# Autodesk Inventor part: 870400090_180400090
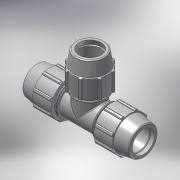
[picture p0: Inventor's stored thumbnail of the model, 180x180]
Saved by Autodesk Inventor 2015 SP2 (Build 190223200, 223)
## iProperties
Created: 2017-02
Part Number: 870400090_180400090
Material: PVC-Piping
Description: PLASSON TEE 90-90-90
Document SubType Name: Modeling
Designer: KIM
Mass: 92.6774 g
Surface Area: 199.44 cm^2
Volume: 66.1981 cm^3
Density: 1.4 g/cm^3
Appearance: Smooth - White
Author: KIM
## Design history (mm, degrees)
derived "87040.ipt"
feature "Solid1::87040.ipt"
tag "TaggingFeature1"
body "Solid1"
other parameters: "d4" = 18.25, "d5" = 54.75, "d7" = 152, "d13" = 120 deg, "d14" = 117, "d15" = 10 deg, "d18" = 4.5, "d19" = 35 deg, "d20" = 17.5 deg, "d21" = 141.36, "d23" = 0, "d25" = 360 deg, "d27" = 3.04, "d42" = 76.65, "d43" = 4.56, "d46" = 2.7, "d63" = 164, "d67" = 114, "d77" = 152, "d78" = 10 deg, "d79" = 219, "d80" = 120 deg, "d81" = 117, "d82" = 18.25, "d85" = 114, "d87" = 7.3, "d88" = 7.3, "d89" = 54.75, "d90" = 76.65, "d98" = 141.36, "d99" = 35 deg, "d100" = 17.5 deg, "d102" = 0, "d103" = 3.04, "d107" = 360 deg, "d109" = 2.7, "d112" = 4.5, "d118" = 360 deg, "d121" = 0, "d128" = 438, "d131" = 81, "d132" = 81, "d133" = 164, "d134" = 3.28, "d152" = 0, "d154" = 0, "d156" = 0, "d158" = 0, "d163" = 16.3, "d165" = 17.94, "d166" = 108.3, "d167" = 108.3, "d168" = 5.98, "d169" = 125.4, "d170" = 2.99, "d171" = 4.485, "d172" = 125.4, "d173" = 5.43333, "d174" = 2.71667, "d175" = 4.075, "d176" = 1.8, "d177" = 4.5, "E_" = 152, "A_" = 219, "l_" = 164, "H_" = 438, "d162" = 32.6, "d164" = 35.88
